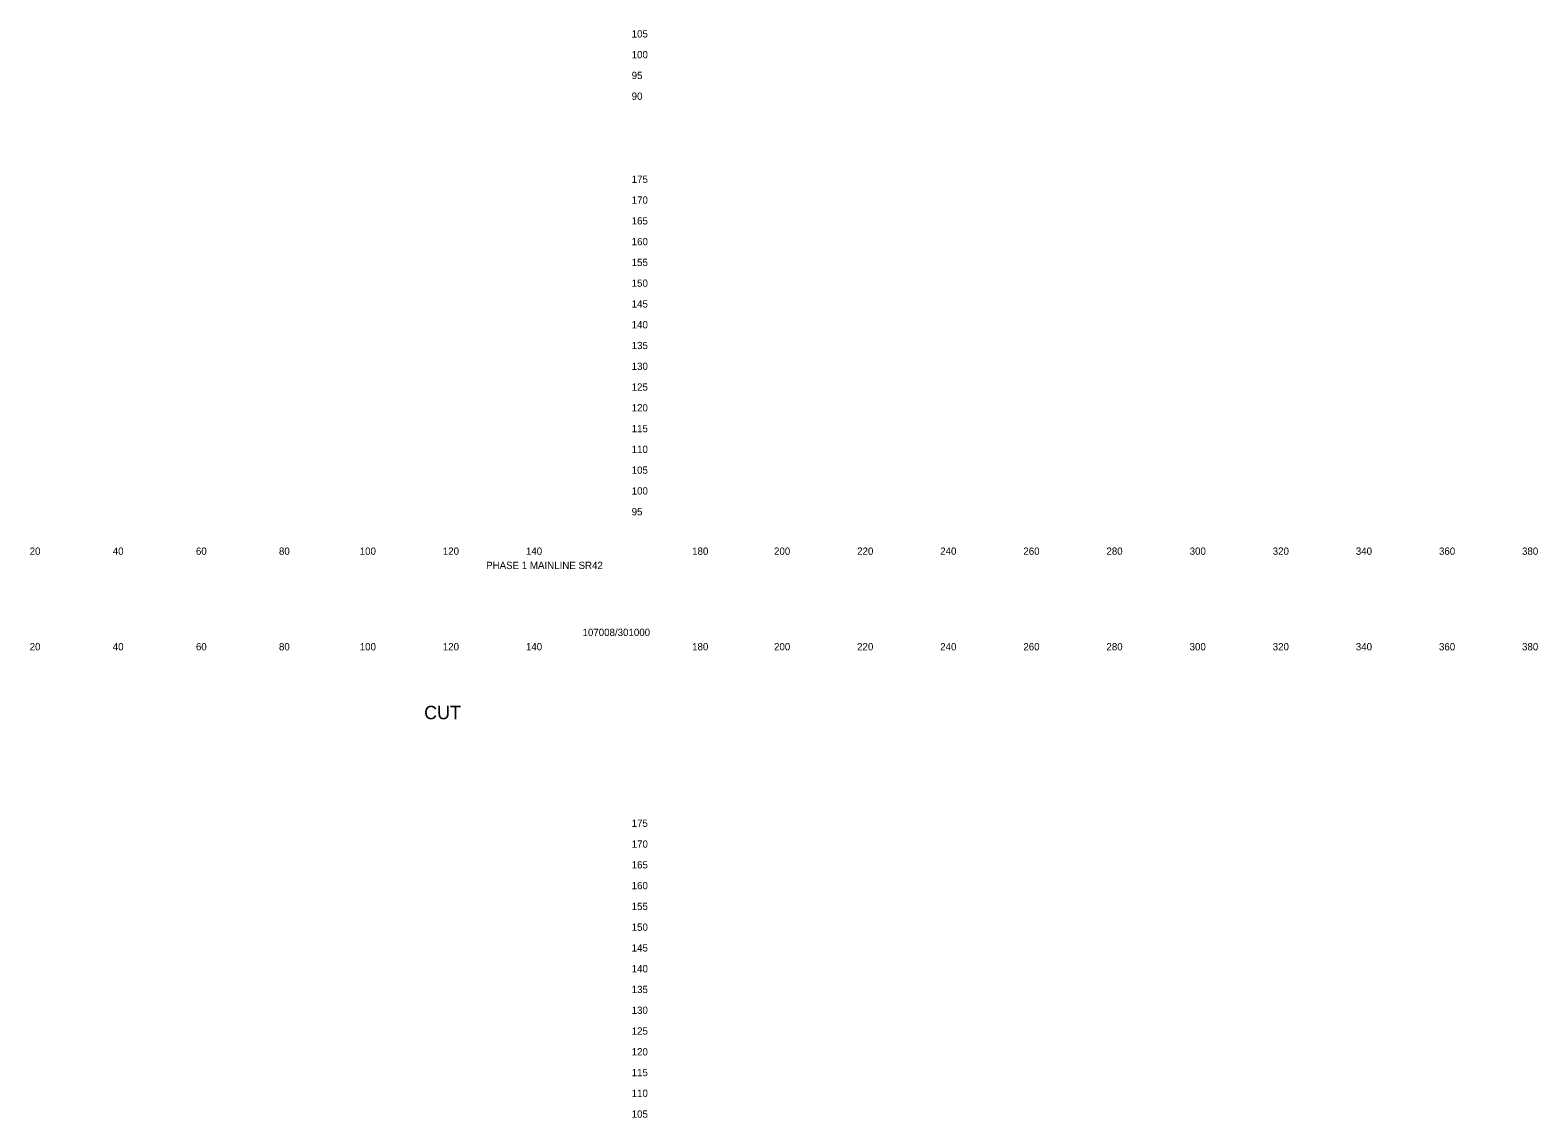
# Model space of a CAD drawing. Extents: x 21281 to 22024, y 6472 to 15198.
# Drawn here: x 21661.4 to 22024.2, y 11399.8 to 11661.6 of the extents above; entities that cross this region are included whole.
import ezdxf

# ---------------------------------------------------------------- set-up
doc = ezdxf.new("R2010")
doc.units = 0
doc.layers.add('XS_SHEET_LABELS_ELEVATION', color=7, linetype='Continuous')
doc.layers.add('XS_SHEET_LABELS_OFFSET', color=7, linetype='Continuous')

msp = doc.modelspace()

# ---------------------------------------------------------------- texts
at = {"layer": 'XS_SHEET_LABELS_ELEVATION'}
for s, p in [('  105  ', (21804.84, 11659.84)), ('  100  ', (21804.84, 11654.84)), ('  95  ', (21804.84, 11649.84)), ('  90  ', (21804.84, 11644.84)), ('  175  ', (21804.84, 11624.84)), ('  170  ', (21804.84, 11619.84)), ('  165  ', (21804.84, 11614.84)), ('  160  ', (21804.84, 11609.84)), ('  155  ', (21804.84, 11604.84)), ('  150  ', (21804.84, 11599.84)), ('  145  ', (21804.84, 11594.84)), ('  140  ', (21804.84, 11589.84)), ('  135  ', (21804.84, 11584.84)), ('  130  ', (21804.84, 11579.84)), ('  125  ', (21804.84, 11574.84)), ('  120  ', (21804.84, 11569.84)), ('  115  ', (21804.84, 11564.84)), ('  110  ', (21804.84, 11559.84)), ('  105  ', (21804.84, 11554.84)), ('  100  ', (21804.84, 11549.84)), ('  95  ', (21804.84, 11544.84)), ('  175  ', (21804.84, 11469.84)), ('  170  ', (21804.84, 11464.84)), ('  165  ', (21804.84, 11459.84)), ('  160  ', (21804.84, 11454.84)), ('  155  ', (21804.84, 11449.84)), ('  150  ', (21804.84, 11444.84)), ('  145  ', (21804.84, 11439.84)), ('  140  ', (21804.84, 11434.84)), ('  135  ', (21804.84, 11429.84)), ('  130  ', (21804.84, 11424.84)), ('  125  ', (21804.84, 11419.84)), ('  120  ', (21804.84, 11414.84)), ('  115  ', (21804.84, 11409.84)), ('  110  ', (21804.84, 11404.84)), ('  105  ', (21804.84, 11399.84))]:
    msp.add_text(s, height=1.75, dxfattribs=at).set_placement(p)
at = {"layer": 'XS_SHEET_LABELS_OFFSET'}
for s, height, p in [('  20  ', 1.75, (21659.95, 11535.34)), ('  40  ', 1.75, (21679.95, 11535.34)), ('  60  ', 1.75, (21699.97, 11535.34)), ('  80  ', 1.75, (21719.95, 11535.34)), ('  100  ', 1.75, (21739.39, 11535.34)), ('  120  ', 1.75, (21759.39, 11535.34)), ('  140  ', 1.75, (21779.39, 11535.34)), ('  180  ', 1.75, (21819.39, 11535.34)), ('  200  ', 1.75, (21839.1, 11535.34)), ('  220  ', 1.75, (21859.1, 11535.34)), ('  240  ', 1.75, (21879.1, 11535.34)), ('  260  ', 1.75, (21899.11, 11535.34)), ('  280  ', 1.75, (21919.1, 11535.34)), ('  300  ', 1.75, (21939.13, 11535.34)), ('  320  ', 1.75, (21959.13, 11535.34)), ('  340  ', 1.75, (21979.13, 11535.34)), ('  360  ', 1.75, (21999.14, 11535.34)), ('  380  ', 1.75, (22019.13, 11535.34)), ('PHASE 1 MAINLINE SR42', 1.75, (21771.11, 11531.92)), ('107008/301000', 1.75, (21794.31, 11515.79)), ('  20  ', 1.75, (21659.95, 11512.34)), ('  40  ', 1.75, (21679.95, 11512.34)), ('  60  ', 1.75, (21699.97, 11512.34)), ('  80  ', 1.75, (21719.95, 11512.34)), ('  100  ', 1.75, (21739.39, 11512.34)), ('  120  ', 1.75, (21759.39, 11512.34)), ('  140  ', 1.75, (21779.39, 11512.34)), ('  180  ', 1.75, (21819.39, 11512.34)), ('  200  ', 1.75, (21839.1, 11512.34)), ('  220  ', 1.75, (21859.1, 11512.34)), ('  240  ', 1.75, (21879.1, 11512.34)), ('  260  ', 1.75, (21899.11, 11512.34)), ('  280  ', 1.75, (21919.1, 11512.34)), ('  300  ', 1.75, (21939.13, 11512.34)), ('  320  ', 1.75, (21959.13, 11512.34)), ('  340  ', 1.75, (21979.13, 11512.34)), ('  360  ', 1.75, (21999.14, 11512.34)), ('  380  ', 1.75, (22019.13, 11512.34)), ('CUT', 3.222, (21756.2, 11495.76))]:
    msp.add_text(s, height=height, dxfattribs=at).set_placement(p)

doc.saveas('drawing.dxf')
